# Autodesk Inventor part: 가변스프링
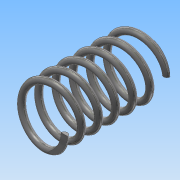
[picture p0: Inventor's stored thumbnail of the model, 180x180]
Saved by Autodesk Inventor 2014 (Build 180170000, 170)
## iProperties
Created: 2018-07
Part Number: 가변스프링
Material: 스테인레스 스틸
Document SubType Name: Modeling
Designer: SEO-12
Density: 8.08 g/cm^3
Appearance: 반연마
Mass: 7.55451 g
Surface Area: 18.9531 cm^2
Volume: 0.934964 cm^3
Author: SEO-12
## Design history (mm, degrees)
sketch "스케치1"
  geometry: L1 (0, 32.152)-(33.453, 32.152); L2 (8, 0)-(0, 0); L3 (0, 0)-(0, 32.152); C1 r 1 at (8, 0); 1 further point
  constraints: 6 end point, 2 coincident, 1 centre point, 1 horizontal, 1 parallel, 1 vertical
  dimensions: "d0" = 2 diameter of C1; "d1" = 16 diameter of C1.centre L3; "d2" = 32.15161 distance between parallel lines of L2 L1 (derived)
feature "코일1" sketch "스케치1" pitch "d3" = 10; turns "d5" = 6; dims "d4" = 32.15161 (= d2), "d6" = 0, angle "d7" = 90 deg, angle "d8" = 90 deg, "d9" = 0, "d10" = 0
sketch "스케치2"
  geometry: L1 (32.152, 16.622)-(0, 16.622); L2 (0, 16.622)-(0, -16.622); L3 (0, -16.622)-(32.152, -16.622); L4 (32.152, -16.622)-(32.152, 16.622); 2 further points
  constraints: 8 end point, 2 parallel, 1 coincident, 1 horizontal, 1 midpoint, 1 perpendicular
  dimensions: "d11" = 32.15161 distance between parallel lines of L2 L4 (derived)
extrude "돌출1" sketch "스케치2" stored distance "d12" = 10; taper "d13" = 0 deg
node "솔리드1"
